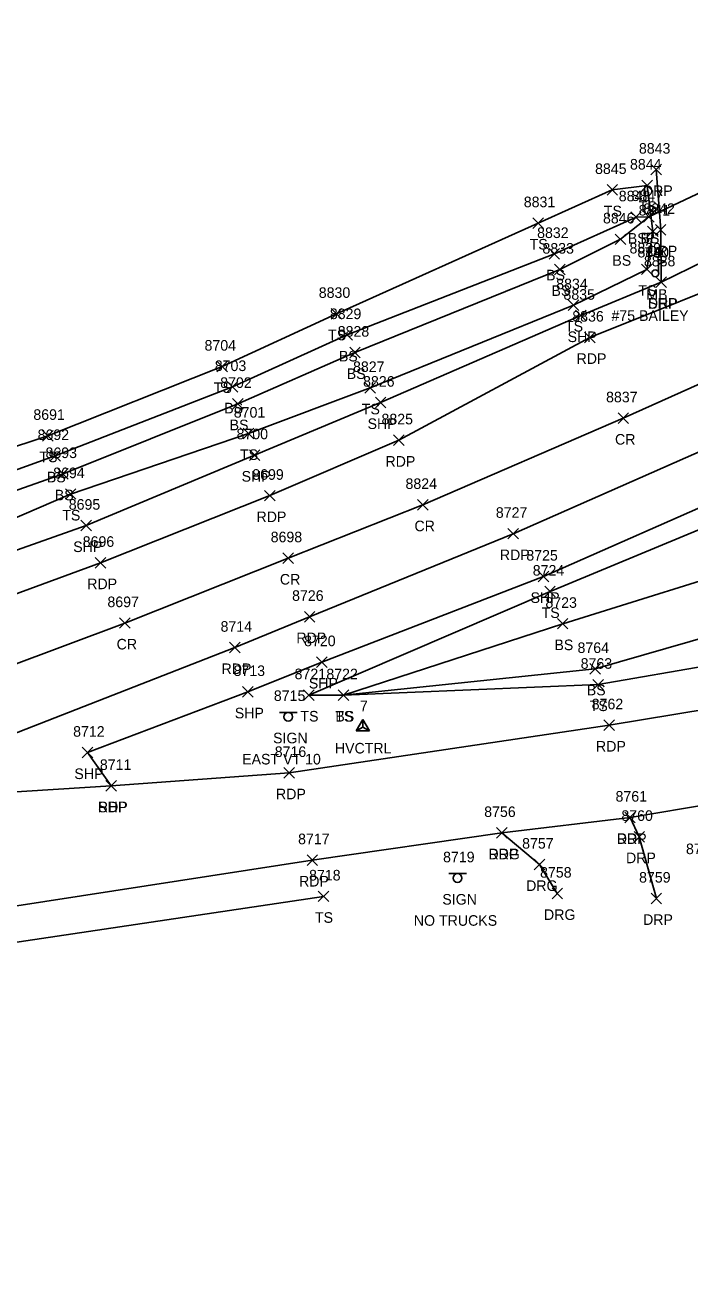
# Model space of a CAD drawing. Extents: x 1611797 to 1633212, y 298978 to 305475.
# Drawn here: x 1628132.7 to 1628258.2, y 304216.5 to 304454.7 of the extents above; entities that cross this region are included whole.
import ezdxf

# ---------------------------------------------------------------- set-up
doc = ezdxf.new("R2010")
doc.units = 0
for name, color, linetype in [('C_A', 7, 'Continuous'), ('C_I', 7, 'Continuous'), ('CPSM', 7, 'Continuous'), ('D_A', 7, 'Continuous'), ('D_I', 7, 'Continuous'), ('D_TIC', 7, 'Continuous'), ('DCP', 7, 'Continuous'), ('L_A', 7, 'Continuous'), ('L_C', 7, 'Continuous'), ('L_I', 7, 'Continuous'), ('L_TIC', 7, 'Continuous'), ('LELB', 7, 'Continuous'), ('LMB', 7, 'Continuous'), ('P_A', 7, 'Continuous'), ('P_I', 7, 'Continuous'), ('P_TIC', 7, 'Continuous'), ('PET', 7, 'Continuous'), ('PRC', 7, 'Continuous'), ('PSP', 7, 'Continuous'), ('R_A', 7, 'Continuous'), ('R_I', 7, 'Continuous'), ('R_TIC', 7, 'Continuous'), ('RDG', 7, 'Continuous'), ('RDP', 7, 'Continuous'), ('S_A', 7, 'Continuous'), ('S_C', 7, 'Continuous'), ('S_I', 7, 'Continuous'), ('SSGN', 7, 'Continuous')]:
    doc.layers.add(name, color=color, linetype=linetype)

msp = doc.modelspace()

# ---------------------------------------------------------------- linework, layer by layer
at = {"layer": 'CPSM'}
for p, q in [((1628195.22, 304321.25), (1628196.47, 304323.41)), ((1628197.72, 304321.25), (1628196.47, 304323.41)), ((1628196.48, 304321.97), (1628196.47, 304323.41)), ((1628195.22, 304321.25), (1628196.48, 304321.97)), ((1628195.22, 304321.25), (1628197.72, 304321.25)), ((1628196.48, 304321.97), (1628196.48, 304321.97)), ((1628196.48, 304321.97), (1628197.72, 304321.25))]:
    msp.add_line(p, q, dxfattribs=at)
at = {"layer": 'D_TIC'}
for points in [[(1628249.5, 304417.42), (1628251.5, 304419.42)], [(1628251.5, 304417.42), (1628249.5, 304419.42)]]:
    msp.add_lwpolyline(points, dxfattribs=at)
at = {"layer": 'DCP'}
msp.add_lwpolyline([(1628250.5, 304418.42), (1628274.4, 304429.72)], dxfattribs=at)
at = {"layer": 'L_TIC'}
for points in [[(1628249.2, 304423.38), (1628251.2, 304425.38)], [(1628251.2, 304423.38), (1628249.2, 304425.38)], [(1628242.6, 304422.54), (1628244.6, 304424.54)], [(1628244.6, 304422.54), (1628242.6, 304424.54)], [(1628242.6, 304422.54), (1628244.6, 304424.54)], [(1628244.6, 304422.54), (1628242.6, 304424.54)], [(1628228.57, 304416.26), (1628230.57, 304418.26)], [(1628230.57, 304416.26), (1628228.57, 304418.26)], [(1628247.08, 304417.37), (1628249.08, 304419.37)], [(1628249.08, 304417.37), (1628247.08, 304419.37)], [(1628247.08, 304417.37), (1628249.08, 304419.37)], [(1628249.08, 304417.37), (1628247.08, 304419.37)], [(1628249.5, 304417.42), (1628251.5, 304419.42)], [(1628251.5, 304417.42), (1628249.5, 304419.42)], [(1628250.26, 304414.69), (1628252.26, 304416.69)], [(1628252.26, 304414.69), (1628250.26, 304416.69)], [(1628244.16, 304413.19), (1628246.16, 304415.19)], [(1628246.16, 304413.19), (1628244.16, 304415.19)], [(1628231.65, 304410.43), (1628233.65, 304412.43)], [(1628233.65, 304410.43), (1628231.65, 304412.43)], [(1628232.66, 304407.48), (1628234.66, 304409.48)], [(1628234.66, 304407.48), (1628232.66, 304409.48)], [(1628249.12, 304407.51), (1628251.12, 304409.51)], [(1628251.12, 304407.51), (1628249.12, 304409.51)], [(1628190.48, 304399.11), (1628192.48, 304401.11)], [(1628192.48, 304399.11), (1628190.48, 304401.11)], [(1628235.26, 304400.75), (1628237.26, 304402.75)], [(1628237.26, 304400.75), (1628235.26, 304402.75)], [(1628192.49, 304395.1), (1628194.49, 304397.1)], [(1628194.49, 304395.1), (1628192.49, 304397.1)], [(1628193.97, 304391.78), (1628195.97, 304393.78)], [(1628195.97, 304391.78), (1628193.97, 304393.78)], [(1628168.88, 304389.14), (1628170.88, 304391.14)], [(1628170.88, 304389.14), (1628168.88, 304391.14)], [(1628170.82, 304385.28), (1628172.82, 304387.28)], [(1628172.82, 304385.28), (1628170.82, 304387.28)], [(1628196.86, 304385.1), (1628198.86, 304387.1)], [(1628198.86, 304385.1), (1628196.86, 304387.1)], [(1628171.83, 304382.09), (1628173.83, 304384.09)], [(1628173.83, 304382.09), (1628171.83, 304384.09)], [(1628135.93, 304376.05), (1628137.93, 304378.05)], [(1628137.93, 304376.05), (1628135.93, 304378.05)], [(1628173.84, 304376.47), (1628175.84, 304378.47)], [(1628175.84, 304376.47), (1628173.84, 304378.47)], [(1628137.3, 304372.24), (1628139.3, 304374.24)], [(1628139.3, 304372.24), (1628137.3, 304374.24)], [(1628138.8, 304368.83), (1628140.8, 304370.83)], [(1628140.8, 304368.83), (1628138.8, 304370.83)], [(1628140.24, 304365.03), (1628142.24, 304367.03)], [(1628142.24, 304365.03), (1628140.24, 304367.03)], [(1628230.83, 304346.6), (1628232.83, 304348.6)], [(1628232.83, 304346.6), (1628230.83, 304348.6)], [(1628233.22, 304340.51), (1628235.22, 304342.51)], [(1628235.22, 304340.51), (1628233.22, 304342.51)], [(1628239.34, 304331.97), (1628241.34, 304333.97)], [(1628241.34, 304331.97), (1628239.34, 304333.97)], [(1628239.92, 304328.99), (1628241.92, 304330.99)], [(1628241.92, 304328.99), (1628239.92, 304330.99)], [(1628185.25, 304327.02), (1628187.25, 304329.02)], [(1628187.25, 304327.02), (1628185.25, 304329.02)], [(1628185.25, 304327.02), (1628187.25, 304329.02)], [(1628187.25, 304327.02), (1628185.25, 304329.02)], [(1628191.82, 304327), (1628193.82, 304329)], [(1628193.82, 304327), (1628191.82, 304329)], [(1628191.82, 304327), (1628193.82, 304329)], [(1628193.82, 304327), (1628191.82, 304329)], [(1628191.82, 304327), (1628193.82, 304329)], [(1628193.82, 304327), (1628191.82, 304329)], [(1628188, 304288.96), (1628190, 304290.96)], [(1628190, 304288.96), (1628188, 304290.96)]]:
    msp.add_lwpolyline(points, dxfattribs=at)
at = {"layer": 'LELB'}
for points in [[(1627877.42, 304292.14), (1627878.12, 304298.49), (1627902.04, 304303.22), (1627948.68, 304314.99), (1627981.71, 304322), (1628004.99, 304332.46), (1628026.5, 304338.9), (1628058.6, 304348.27), (1628099.75, 304364.74), (1628136.93, 304377.05), (1628169.88, 304390.14), (1628191.48, 304400.11), (1628229.57, 304417.26), (1628243.6, 304423.54)], [(1627878.22, 304288.02), (1627879.88, 304285.51), (1627905.6, 304291.96), (1627949.91, 304303.86), (1627984.15, 304312.81), (1628015.57, 304322.05), (1628032.64, 304325.52), (1628058.08, 304336.19), (1628102.92, 304349.5), (1628141.24, 304366.03), (1628174.84, 304377.47), (1628197.86, 304386.1), (1628236.26, 304401.75), (1628250.12, 304408.51), (1628251.26, 304415.69), (1628250.2, 304424.38), (1628243.6, 304423.54)], [(1627880.26, 304295.08), (1627878.68, 304290.78), (1627879.29, 304288.56), (1627905.01, 304294.93), (1627949.21, 304307.19), (1627983.28, 304317.8), (1628000.64, 304322.62), (1628004.09, 304323.49), (1628006.75, 304324.26), (1628026.79, 304331.8), (1628056.4, 304340.14), (1628100.73, 304356.02), (1628139.8, 304369.83), (1628172.83, 304383.09), (1628194.97, 304392.78), (1628233.66, 304408.48), (1628245.16, 304414.19), (1628250.5, 304418.42), (1628248.08, 304418.37)], [(1627878.68, 304290.78), (1627904.3, 304298.29), (1627948.96, 304309.39), (1627982.59, 304319.17), (1628001.32, 304325.53), (1628006.76, 304327.6), (1628026.58, 304334.26), (1628055.44, 304341.97), (1628100.13, 304359.49), (1628138.3, 304373.24), (1628171.82, 304386.28), (1628193.49, 304396.1), (1628232.65, 304411.43), (1628248.08, 304418.37)], [(1628186.25, 304328.02), (1628231.83, 304347.6), (1628268.7, 304362.9), (1628308.54, 304379.8), (1628337.74, 304388.15), (1628354.44, 304378.76), (1628365.87, 304371.34), (1628370.69, 304365.3)], [(1628192.82, 304328), (1628234.22, 304341.51), (1628273.34, 304353.72), (1628312.9, 304367.44), (1628340.59, 304377.02), (1628341.52, 304375.56)], [(1628192.82, 304328), (1628240.34, 304332.97), (1628285.47, 304345.93), (1628326.74, 304356.31), (1628359.2, 304357.4), (1628346.85, 304366.15), (1628342.44, 304371.63)], [(1628186.25, 304328.02), (1628192.82, 304328), (1628240.92, 304329.99), (1628284.67, 304337.55), (1628329.55, 304349.3), (1628359.4, 304352.78), (1628370.69, 304365.3)], [(1627861.41, 304216.51), (1627862.27, 304227.46), (1627868.26, 304234.09), (1627889.03, 304237.87), (1627915.19, 304243.17), (1627972.54, 304253.43), (1627994.96, 304257.24), (1628029.82, 304264.96), (1628070.17, 304272.27), (1628093.21, 304277.24), (1628123.82, 304280.25), (1628189, 304289.96)]]:
    msp.add_lwpolyline(points, dxfattribs=at)
at = {"layer": 'LMB'}
for p, q in [((1628252.36, 304410.36), (1628253.65, 304409.98)), ((1628252.36, 304407.77), (1628252.36, 304410.36)), ((1628252.36, 304409.46), (1628253.64, 304409.97)), ((1628251.71, 304407.76), (1628251.71, 304407.76))]:
    msp.add_line(p, q, dxfattribs=at)
msp.add_circle((1628251.71, 304407.76), 0.656, dxfattribs=at)
at = {"layer": 'P_TIC'}
for points in [[(1628251.83, 304405.07), (1628253.83, 304407.07)], [(1628253.83, 304405.07), (1628251.83, 304407.07)], [(1628236.63, 304398.76), (1628238.63, 304400.76)], [(1628238.63, 304398.76), (1628236.63, 304400.76)], [(1628238.35, 304394.63), (1628240.35, 304396.63)], [(1628240.35, 304394.63), (1628238.35, 304396.63)], [(1628198.82, 304382.32), (1628200.82, 304384.32)], [(1628200.82, 304382.32), (1628198.82, 304384.32)], [(1628244.68, 304379.37), (1628246.68, 304381.37)], [(1628246.68, 304379.37), (1628244.68, 304381.37)], [(1628202.24, 304375.2), (1628204.24, 304377.2)], [(1628204.24, 304375.2), (1628202.24, 304377.2)], [(1628175.01, 304372.38), (1628177.01, 304374.38)], [(1628177.01, 304372.38), (1628175.01, 304374.38)], [(1628177.88, 304364.72), (1628179.88, 304366.72)], [(1628179.88, 304364.72), (1628177.88, 304366.72)], [(1628206.78, 304362.99), (1628208.78, 304364.99)], [(1628208.78, 304362.99), (1628206.78, 304364.99)], [(1628143.19, 304359.06), (1628145.19, 304361.06)], [(1628145.19, 304359.06), (1628143.19, 304361.06)], [(1628223.85, 304357.53), (1628225.85, 304359.53)], [(1628225.85, 304357.53), (1628223.85, 304359.53)], [(1628145.89, 304352.04), (1628147.89, 304354.04)], [(1628147.89, 304352.04), (1628145.89, 304354.04)], [(1628181.35, 304352.91), (1628183.35, 304354.91)], [(1628183.35, 304352.91), (1628181.35, 304354.91)], [(1628229.61, 304349.44), (1628231.61, 304351.44)], [(1628231.61, 304349.44), (1628229.61, 304351.44)], [(1628185.4, 304341.83), (1628187.4, 304343.83)], [(1628187.4, 304341.83), (1628185.4, 304343.83)], [(1628150.5, 304340.64), (1628152.5, 304342.64)], [(1628152.5, 304340.64), (1628150.5, 304342.64)], [(1628171.26, 304335.99), (1628173.26, 304337.99)], [(1628173.26, 304335.99), (1628171.26, 304337.99)], [(1628187.71, 304333.26), (1628189.71, 304335.26)], [(1628189.71, 304333.26), (1628187.71, 304335.26)], [(1628173.72, 304327.62), (1628175.72, 304329.62)], [(1628175.72, 304327.62), (1628173.72, 304329.62)], [(1628242.02, 304321.33), (1628244.02, 304323.33)], [(1628244.02, 304321.33), (1628242.02, 304323.33)], [(1628143.4, 304316.14), (1628145.4, 304318.14)], [(1628145.4, 304316.14), (1628143.4, 304318.14)], [(1628181.55, 304312.31), (1628183.55, 304314.31)], [(1628183.55, 304312.31), (1628181.55, 304314.31)], [(1628147.89, 304309.86), (1628149.89, 304311.86)], [(1628149.89, 304309.86), (1628147.89, 304311.86)], [(1628147.89, 304309.86), (1628149.89, 304311.86)], [(1628149.89, 304309.86), (1628147.89, 304311.86)], [(1628245.95, 304303.87), (1628247.95, 304305.87)], [(1628247.95, 304303.87), (1628245.95, 304305.87)], [(1628221.7, 304300.96), (1628223.7, 304302.96)], [(1628223.7, 304300.96), (1628221.7, 304302.96)], [(1628185.91, 304295.82), (1628187.91, 304297.82)], [(1628187.91, 304295.82), (1628185.91, 304297.82)]]:
    msp.add_lwpolyline(points, dxfattribs=at)
at = {"layer": 'PET'}
for points in [[(1627804.93, 304257.83), (1627871.73, 304271.16), (1627912.59, 304279.87), (1627952.18, 304289.63), (1627988.87, 304299.65), (1628036.27, 304314.36), (1628064.89, 304323.89), (1628106.09, 304338.02), (1628146.89, 304353.04), (1628178.88, 304365.72), (1628203.24, 304376.2), (1628239.35, 304395.63), (1628307.27, 304422.84), (1628351.46, 304445.9), (1628391.91, 304468.24), (1628442.08, 304497.28), (1628474.72, 304517.21), (1628486.15, 304524.53), (1628539.34, 304558.37), (1628672.08, 304644.96)], [(1627810.3, 304233.75), (1627865.14, 304244.67), (1627887.51, 304249.2), (1627919.75, 304256.3), (1627968.24, 304266.92), (1627982, 304270.08), (1628025.8, 304282.81), (1628091.15, 304305.91), (1628127.23, 304319.42), (1628172.26, 304336.99), (1628186.4, 304342.83), (1628224.85, 304358.53), (1628263.27, 304375.45), (1628301.66, 304393.36), (1628314.71, 304398.73), (1628435.17, 304464.05), (1628474.08, 304488.85), (1628500.64, 304505.36), (1628549.92, 304536.59), (1628643.11, 304597.45)], [(1628091.15, 304305.91), (1628128, 304309.51), (1628148.89, 304310.86), (1628182.55, 304313.31), (1628243.02, 304322.33), (1628286.89, 304329.59), (1628334.88, 304337.13), (1628358.67, 304340.75), (1628369.91, 304350.06), (1628380.04, 304358.69)], [(1627982, 304270.08), (1628027.65, 304274.59), (1628078.62, 304279.32), (1628124.05, 304287.09), (1628186.91, 304296.82), (1628222.7, 304301.96), (1628246.95, 304304.87), (1628262.66, 304307.51), (1628290.41, 304312.26), (1628340.56, 304319.95), (1628375.05, 304325.33), (1628408.7, 304331.21), (1628463.4, 304340.12)]]:
    msp.add_lwpolyline(points, dxfattribs=at)
at = {"layer": 'PRC'}
msp.add_lwpolyline([(1627805.83, 304244.92), (1627874.04, 304257.97), (1627915.41, 304267.12), (1627953.91, 304276.61), (1627992.17, 304287.01), (1628041.6, 304302.51), (1628071.46, 304312.51), (1628106.81, 304324.94), (1628151.5, 304341.64), (1628182.35, 304353.91), (1628207.78, 304363.99), (1628245.68, 304380.37), (1628274.85, 304393.46), (1628311.84, 304411.21), (1628357.26, 304434.55), (1628397.17, 304456.52), (1628447.84, 304486.53), (1628480.37, 304506.37), (1628493.94, 304514.67), (1628544.35, 304546.87), (1628636.51, 304607.63)], dxfattribs=at)
at = {"layer": 'PSP'}
for points in [[(1627804.39, 304265.42), (1627852.07, 304273.99), (1627870.38, 304278.52), (1627907.16, 304286.52), (1627951.04, 304297.7), (1627985.89, 304307.24), (1628033.67, 304321.93), (1628060.73, 304329.87), (1628103.74, 304345.79), (1628144.19, 304360.06), (1628176.01, 304373.38), (1628199.82, 304383.32), (1628237.63, 304399.76), (1628252.83, 304406.07), (1628285.85, 304422.19), (1628303.97, 304430.64), (1628347.35, 304452.9), (1628388.22, 304474.79), (1628437.92, 304504.47), (1628470.55, 304523.84), (1628481.56, 304530.46), (1628534.86, 304565.19), (1628598, 304608.08), (1628616.57, 304620.02)], [(1628148.89, 304310.86), (1628144.4, 304317.14), (1628174.72, 304328.62), (1628188.71, 304334.26), (1628230.61, 304350.44), (1628267.21, 304366.57), (1628306.52, 304382.81), (1628332.16, 304394.64)]]:
    msp.add_lwpolyline(points, dxfattribs=at)
at = {"layer": 'R_TIC'}
for points in [[(1628250.89, 304426.38), (1628252.89, 304428.38)], [(1628252.89, 304426.38), (1628250.89, 304428.38)], [(1628251.74, 304414.98), (1628253.74, 304416.98)], [(1628253.74, 304414.98), (1628251.74, 304416.98)], [(1628251.83, 304405.07), (1628253.83, 304407.07)], [(1628253.83, 304405.07), (1628251.83, 304407.07)], [(1628245.95, 304303.87), (1628247.95, 304305.87)], [(1628247.95, 304303.87), (1628245.95, 304305.87)], [(1628221.7, 304300.96), (1628223.7, 304302.96)], [(1628223.7, 304300.96), (1628221.7, 304302.96)], [(1628247.7, 304300.23), (1628249.7, 304302.23)], [(1628249.7, 304300.23), (1628247.7, 304302.23)], [(1628228.82, 304294.98), (1628230.82, 304296.98)], [(1628230.82, 304294.98), (1628228.82, 304296.98)], [(1628232.21, 304289.5), (1628234.21, 304291.5)], [(1628234.21, 304289.5), (1628232.21, 304291.5)], [(1628250.92, 304288.56), (1628252.92, 304290.56)], [(1628252.92, 304288.56), (1628250.92, 304290.56)]]:
    msp.add_lwpolyline(points, dxfattribs=at)
at = {"layer": 'RDG'}
msp.add_lwpolyline([(1628222.7, 304301.96), (1628229.82, 304295.98), (1628233.21, 304290.5)], dxfattribs=at)
at = {"layer": 'RDP'}
for points in [[(1628252.83, 304406.07), (1628252.74, 304415.98), (1628251.89, 304427.38)], [(1628251.92, 304289.56), (1628248.7, 304301.23), (1628246.95, 304304.87)]]:
    msp.add_lwpolyline(points, dxfattribs=at)
at = {"layer": 'SSGN'}
for p, q in [((1628180.71, 304324.75), (1628184.04, 304324.75)), ((1628182.36, 304323.92), (1628182.36, 304323.92)), ((1628212.7, 304294.26), (1628216.03, 304294.26)), ((1628214.34, 304293.42), (1628214.34, 304293.42))]:
    msp.add_line(p, q, dxfattribs=at)
for centre in [(1628182.36, 304323.92), (1628214.34, 304293.42)]:
    msp.add_circle(centre, 0.833, dxfattribs=at)

# ---------------------------------------------------------------- texts
at = {"layer": 'C_A'}
msp.add_text('HVCTRL', height=2, dxfattribs=at).set_placement((1628191.17, 304316.97))
at = {"layer": 'C_I'}
msp.add_text('7', height=2, dxfattribs=at).set_placement((1628195.91, 304324.97))
at = {"layer": 'D_A'}
msp.add_text('P', height=2, dxfattribs=at).set_placement((1628249.88, 304413.42))
at = {"layer": 'D_I'}
msp.add_text('8847', height=2, dxfattribs=at).set_placement((1628247.24, 304421.42))
at = {"layer": 'L_A'}
for s, p in [('TS', (1628242, 304418.54)), ('TS', (1628242, 304418.54)), ('TS', (1628248.61, 304419.38)), ('BS', (1628246.52, 304413.37)), ('BS', (1628246.52, 304413.37)), ('BS', (1628248.94, 304413.42)), ('TS', (1628227.97, 304412.26)), ('BS', (1628243.6, 304409.19)), ('TS', (1628249.67, 304410.69)), ('BS', (1628231.09, 304406.43)), ('BS', (1628232.1, 304403.48)), ('TS', (1628248.53, 304403.51)), ('MB', (1628250.01, 304402.76)), ('TS', (1628234.66, 304396.75)), ('TS', (1628189.89, 304395.11)), ('BS', (1628191.93, 304391.1)), ('BS', (1628193.41, 304387.78)), ('TS', (1628168.29, 304385.14)), ('BS', (1628170.26, 304381.28)), ('TS', (1628196.26, 304381.1)), ('BS', (1628171.28, 304378.09)), ('TS', (1628135.34, 304372.05)), ('TS', (1628173.25, 304372.47)), ('BS', (1628136.74, 304368.24)), ('BS', (1628138.24, 304364.83)), ('TS', (1628139.65, 304361.03)), ('TS', (1628230.24, 304342.6)), ('BS', (1628232.66, 304336.51)), ('BS', (1628238.78, 304327.97)), ('TS', (1628184.66, 304323.02)), ('TS', (1628184.66, 304323.02)), ('TS', (1628191.23, 304323)), ('BS', (1628191.26, 304323)), ('BS', (1628191.26, 304323)), ('TS', (1628239.33, 304324.99)), ('TS', (1628187.41, 304284.96))]:
    msp.add_text(s, height=2, dxfattribs=at).set_placement(p)
at = {"layer": 'L_C'}
msp.add_text('#75 BAILEY', height=2, dxfattribs=at).set_placement((1628243.44, 304398.76))
at = {"layer": 'L_I'}
for s, p in [('8845', (1628240.34, 304426.54)), ('8845', (1628240.34, 304426.54)), ('8844', (1628246.94, 304427.38)), ('8848', (1628244.82, 304421.37)), ('8848', (1628244.82, 304421.37)), ('8847', (1628247.24, 304421.42)), ('8831', (1628226.87, 304420.26)), ('8841', (1628248.57, 304418.69)), ('8846', (1628241.84, 304417.19)), ('8832', (1628229.39, 304414.43)), ('8833', (1628230.4, 304411.48)), ('8839', (1628246.85, 304411.51)), ('8840', (1628248.36, 304410.76)), ('8834', (1628233, 304404.75)), ('8830', (1628188.13, 304403.11)), ('8829', (1628190.22, 304399.1)), ('8828', (1628191.71, 304395.78)), ('8704', (1628166.54, 304393.14)), ('8703', (1628168.48, 304389.28)), ('8827', (1628194.6, 304389.1)), ('8702', (1628169.5, 304386.09)), ('8691', (1628134.19, 304380.05)), ('8701', (1628172.07, 304380.47)), ('8692', (1628134.99, 304376.24)), ('8693', (1628136.49, 304372.83)), ('8694', (1628137.94, 304369.03)), ('8724', (1628228.57, 304350.6)), ('8723', (1628230.96, 304344.51)), ('8764', (1628237.03, 304335.97)), ('8763', (1628237.62, 304332.99)), ('8721', (1628183.56, 304331.02)), ('8721', (1628183.56, 304331.02)), ('8722', (1628189.56, 304331)), ('8722', (1628189.56, 304331)), ('8722', (1628189.56, 304331)), ('8718', (1628186.3, 304292.96))]:
    msp.add_text(s, height=2, dxfattribs=at).set_placement(p)
at = {"layer": 'P_A'}
for s, p in [('SHP', (1628250.37, 304401.07)), ('SHP', (1628235.16, 304394.76)), ('RDP', (1628236.84, 304390.63)), ('SHP', (1628197.35, 304378.32)), ('CR', (1628244.11, 304375.37)), ('RDP', (1628200.73, 304371.2)), ('SHP', (1628173.55, 304368.38)), ('RDP', (1628176.36, 304360.72)), ('CR', (1628206.21, 304358.99)), ('SHP', (1628141.72, 304355.06)), ('RDP', (1628222.34, 304353.53)), ('RDP', (1628144.37, 304348.04)), ('CR', (1628180.78, 304348.91)), ('SHP', (1628228.15, 304345.44)), ('RDP', (1628183.89, 304337.83)), ('CR', (1628149.93, 304336.64)), ('RDP', (1628169.75, 304331.99)), ('SHP', (1628186.24, 304329.26)), ('SHP', (1628172.26, 304323.62)), ('RDP', (1628240.51, 304317.33)), ('SHP', (1628141.94, 304312.14)), ('RDP', (1628180.04, 304308.31)), ('SHP', (1628146.43, 304305.86)), ('RDP', (1628146.38, 304305.86)), ('RDP', (1628244.44, 304299.87)), ('RDP', (1628220.19, 304296.96)), ('RDP', (1628184.4, 304291.82))]:
    msp.add_text(s, height=2, dxfattribs=at).set_placement(p)
at = {"layer": 'P_I'}
for s, p in [('8838', (1628249.57, 304409.07)), ('8835', (1628234.37, 304402.76)), ('8836', (1628236.04, 304398.63)), ('8826', (1628196.5, 304386.32)), ('8837', (1628242.42, 304383.37)), ('8825', (1628199.98, 304379.2)), ('8700', (1628172.59, 304376.38)), ('8699', (1628175.56, 304368.72)), ('8824', (1628204.52, 304366.99)), ('8695', (1628140.88, 304363.06)), ('8727', (1628221.59, 304361.53)), ('8698', (1628179.04, 304356.91)), ('8696', (1628143.52, 304356.04)), ('8725', (1628227.35, 304353.44)), ('8697', (1628148.19, 304344.64)), ('8726', (1628183.09, 304345.83)), ('8714', (1628169.57, 304339.99)), ('8720', (1628185.36, 304337.26)), ('8713', (1628172.03, 304331.62)), ('8762', (1628239.71, 304325.33)), ('8712', (1628141.71, 304320.14)), ('8716', (1628179.81, 304316.31)), ('8711', (1628146.76, 304313.86)), ('8711', (1628146.76, 304313.86)), ('8761', (1628244.21, 304307.87)), ('8756', (1628219.39, 304304.96)), ('8717', (1628184.22, 304299.82))]:
    msp.add_text(s, height=2, dxfattribs=at).set_placement(p)
at = {"layer": 'R_A'}
for s, p in [('DRP', (1628249.37, 304422.38)), ('DRP', (1628250.23, 304410.98)), ('DRP', (1628250.32, 304401.07)), ('DRP', (1628244.44, 304299.87)), ('DRG', (1628220.19, 304296.96)), ('DRP', (1628246.19, 304296.23)), ('DRG', (1628227.31, 304290.98)), ('DRG', (1628230.69, 304285.5)), ('DRP', (1628249.41, 304284.56))]:
    msp.add_text(s, height=2, dxfattribs=at).set_placement(p)
at = {"layer": 'R_I'}
for s, p in [('8843', (1628248.63, 304430.38)), ('8842', (1628249.48, 304418.98)), ('8838', (1628249.57, 304409.07)), ('8761', (1628244.21, 304307.87)), ('8756', (1628219.39, 304304.96)), ('8760', (1628245.31, 304304.23)), ('8757', (1628226.56, 304298.98)), ('8765', (1628257.52, 304297.94)), ('8758', (1628229.95, 304293.5)), ('8759', (1628248.66, 304292.56))]:
    msp.add_text(s, height=2, dxfattribs=at).set_placement(p)
at = {"layer": 'S_A'}
for p in [(1628179.49, 304318.9), (1628211.48, 304288.4)]:
    msp.add_text('SIGN', height=2, dxfattribs=at).set_placement(p)
at = {"layer": 'S_C'}
for s, p in [('EAST VT 10', (1628173.65, 304314.9)), ('NO TRUCKS', (1628206.09, 304284.4))]:
    msp.add_text(s, height=2, dxfattribs=at).set_placement(p)
at = {"layer": 'S_I'}
for s, p in [('8715', (1628179.64, 304326.9)), ('8719', (1628211.62, 304296.4))]:
    msp.add_text(s, height=2, dxfattribs=at).set_placement(p)

doc.saveas('drawing.dxf')
